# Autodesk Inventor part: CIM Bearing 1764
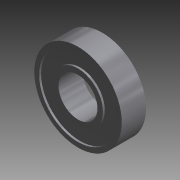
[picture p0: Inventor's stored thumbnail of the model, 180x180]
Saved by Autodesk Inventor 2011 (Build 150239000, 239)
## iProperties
Shininess: 60.0
Length Units: 11272
Angle Units: 11279
Time Units: 11290
Mass Units: 11286
Length Display Precision: 3
Angle Display Precision: 2
Company: FirstCad Library
Created: 2001-10
Part Number: CIM Bearing 1764
Material: Stainless Steel, Austenitic
Document SubType Name: Modeling
Description: 1/2" Dia Bearing
Designer: Ed Sparks
Mass: 29.7504 g
Surface Area: 22.247 cm^2
Volume: 3.7049 cm^3
Density: 8.03 g/cm^3
Density: 0.0
Volumn: 0.0
Area: 0.0
PropertySet Name: Model Information
Control State: 0
Master: False
Checked Out: False
Author: Ed Sparks
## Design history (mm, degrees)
node "Extrusion1" dims "d35" = 7.9375, "d36" = 0
  sketch "Sketch1"
    geometry: C1 r 8.128 at (0, 0); C2 r 6.35 at (0, 0)
    constraints: 2 centre point, 1 coincident
    dimensions: "d32" = 12.7 diameter of C2; "d33" = 16.256 diameter of C1
workplane "Work Plane1"
node "Extrusion2" dims "d39" = 6.6675, "d40" = 0
  sketch "Sketch2"
    geometry: C1 r 12.7 at (0, 0); C2 r 8.128 at (0, 0)
    constraints: 2 centre point, 1 coincident
    dimensions: "d37" = 25.4 diameter of C1; "d38" = 16.256 diameter of C2
node "Extrusion3" dims "d43" = 7.9375, "d44" = 0
  sketch "Sketch3"
    geometry: C1 r 12.7 at (0, 0); C2 r 14.287 at (0, 0)
    constraints: 2 centre point, 1 coincident
    dimensions: "d41" = 25.4 diameter of C1; "d42" = 28.575 diameter of C2
body "Solid1"
other parameters: "d9" = 1.4241 (derived)
